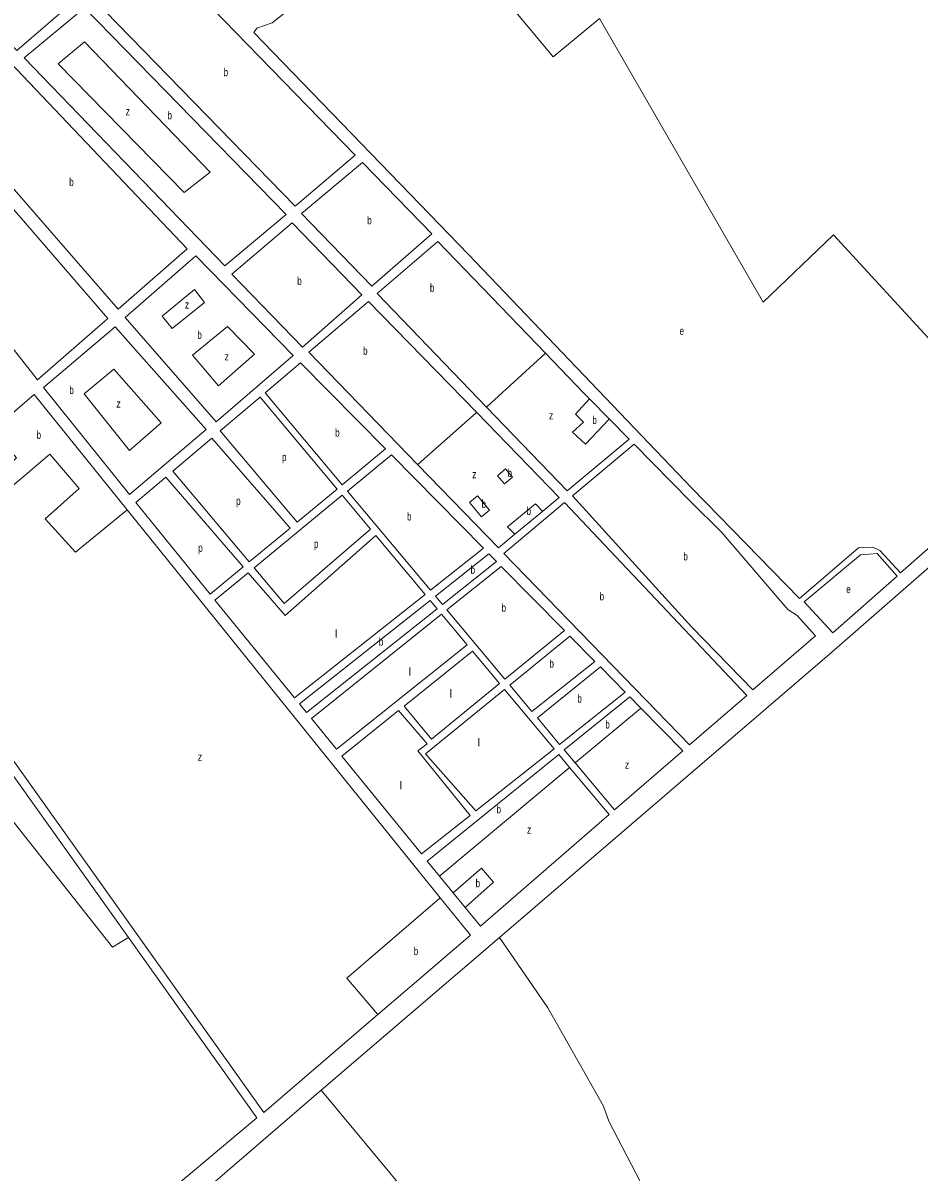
# Model space of a CAD drawing. Extents: x 639657 to 671642, y 222838 to 252123.
# Drawn here: x 656164 to 657284, y 229541 to 230977 of the extents above; entities that cross this region are included whole.
import ezdxf

# ---------------------------------------------------------------- set-up
doc = ezdxf.new("R2010")
doc.units = 0
doc.header["$LTSCALE"] = 4
doc.layers.add('1', color=7, linetype='Continuous', lineweight=13)
doc.layers.add('21', color=7, linetype='Continuous', lineweight=13)
doc.layers.add('7', color=7, linetype='Continuous')

msp = doc.modelspace()

# ---------------------------------------------------------------- linework, layer by layer
at = {"layer": '1'}
for p, q in [((656466.939, 230514.9), (656563.274, 230399.934)), ((656460.885, 230509.763), (656410.874, 230467.339)), ((656460.885, 230509.763), (656556.984, 230394.728)), ((656834.7, 230384.405), (656731.124, 230490.676)), ((656400.479, 230458.522), (656351.528, 230416.996)), ((656400.479, 230458.522), (656498.204, 230346.074)), ((656410.874, 230467.339), (656506.996, 230353.351)), ((656844.557, 230392.588), (656922.134, 230457)), ((656563.274, 230399.934), (656617.528, 230444.841)), ((656851.041, 230386.083), (656928.324, 230450.708)), ((656569.813, 230392.13), (656624.857, 230437.403)), ((656739.864, 230320.684), (656624.857, 230437.403)), ((656351.528, 230416.996), (656446.958, 230303.656)), ((656342.85, 230409.634), (656439.588, 230297.556)), ((656453.211, 230296.229), (656563.495, 230386.934)), ((656506.996, 230353.351), (656556.984, 230394.728)), ((656563.495, 230386.934), (656598.727, 230344.759)), ((656569.813, 230392.13), (656673.59, 230268.281)), ((656765.331, 230314.412), (656841.091, 230377.763)), ((657068.838, 230136.938), (656841.091, 230377.763)), ((656446.958, 230303.656), (656498.204, 230346.074)), ((656605.389, 230336.784), (656666.982, 230263.055)), ((656673.59, 230268.281), (656739.864, 230320.684)), ((656679.79, 230260.882), (656746.571, 230313.877)), ((656756.142, 230304.163), (656746.571, 230313.877)), ((656765.331, 230314.412), (656997.493, 230075.051)), ((656398.351, 230263.424), (656439.588, 230297.556)), ((656688.536, 230250.444), (656756.142, 230304.163)), ((656694.223, 230243.658), (656762.094, 230298.122)), ((656841.125, 230217.915), (656762.094, 230298.122)), ((656404.353, 230256.045), (656445.913, 230290.228)), ((656404.353, 230256.045), (656503.684, 230133.934)), ((656503.684, 230133.934), (656666.982, 230263.055)), ((656510.013, 230126.152), (656673.18, 230255.635)), ((656673.18, 230255.635), (656681.913, 230245.182)), ((656679.79, 230260.882), (656688.536, 230250.444)), ((656518.689, 230115.487), (656681.913, 230245.182)), ((656694.223, 230243.658), (656766.714, 230157.147)), ((656524.933, 230107.811), (656687.615, 230238.356)), ((656687.615, 230238.356), (656719.63, 230200.033)), ((656841.125, 230217.915), (656766.714, 230157.147)), ((656847.837, 230211.103), (656772.829, 230149.847)), ((656879.197, 230179.276), (656847.837, 230211.103)), ((656556.046, 230069.563), (656719.63, 230200.033)), ((656640.632, 230123.355), (656726.173, 230192.201)), ((656726.173, 230192.201), (656760.022, 230151.683)), ((656800.522, 230116.799), (656879.197, 230179.276)), ((656807.23, 230108.793), (656886.01, 230172.362)), ((656917.104, 230140.806), (656886.01, 230172.362)), ((656766.128, 230144.374), (656667.597, 230063.908)), ((656760.022, 230151.683), (656674.921, 230082.184)), ((656766.128, 230144.374), (656828.094, 230070.198)), ((656772.829, 230149.847), (656800.522, 230116.799)), ((656834.988, 230075.667), (656917.104, 230140.806)), ((656510.013, 230126.152), (656518.689, 230115.487)), ((656840.884, 230068.63), (656922.804, 230135.02)), ((656997.493, 230075.051), (657068.838, 230136.938)), ((656563.068, 230060.931), (656633.741, 230117.809)), ((656633.741, 230117.809), (656669.368, 230076.412)), ((656640.632, 230123.355), (656674.921, 230082.184)), ((656524.933, 230107.811), (656556.046, 230069.563)), ((656807.23, 230108.793), (656834.988, 230075.667)), ((656730.177, 229992.524), (656828.094, 230070.198)), ((656563.068, 230060.931), (656662.429, 229938.783)), ((656667.597, 230063.908), (656730.177, 229992.524)), ((656669.674, 229929.876), (656834.039, 230063.083)), ((656662.429, 229938.783), (656723.134, 229986.938)), ((656736.052, 229848.275), (656896.919, 229987.813)), ((656667.82, 229789.09), (656723.507, 229837.393))]:
    msp.add_line(p, q, dxfattribs=at)
for points in [[(656231.52, 231007.4), (656156.92, 230942.74), (656030.9, 231074.47), (656105.5, 231139.55)], [(656251.18, 231008.67), (656325.79, 231073.33), (656579.74, 230812.26), (656504.7, 230748.23)], [(656166.13, 230933.81), (656241.2, 230996.12), (656493.19, 230737.82), (656416.86, 230673.55)], [(655984, 230783.98), (656182.67, 230531.42), (656270.29, 230607.82), (656061.4, 230849.76)], [(656512.3, 230739.27), (656600.34, 230648.27), (656675.37, 230713.81), (656588.63, 230803.1)], [(656513.8, 230572.3), (656587.98, 230637.42), (656500.8, 230727.56), (656425.33, 230663.52)], [(656502.13, 230561.8), (656405.75, 230478.75), (656291.97, 230609.3), (656380.44, 230686.35)], [(656393.24, 230468.99), (656297.76, 230388.07), (656190.28, 230521.6), (656279.62, 230597.59)], [(657256.82, 230285.76), (657176.49, 230215.12), (657140.47, 230253.8), (657211, 230312.6), (657232.02, 230314.39)]]:
    msp.add_lwpolyline(points, close=True, dxfattribs=at)
for points in [[(656713.006, 231072.175), (656690.32, 231055.59), (656656.04, 231046.06), (656645.94, 231046.4), (656621.85, 231048.99), (656588.33, 231049.99), (656562.8, 231046.55), (656475.94, 230977.58), (656456.79, 230970.95), (656453.1, 230965.47), (656721.14, 230687.77), (657000.35, 230395.98), (657134.77, 230258.17), (657208.41, 230321.35), (657226.66, 230322.21), (657235.15, 230318.12), (657261.23, 230289.95), (657389.09, 230402.13), (657419.13, 230421.32), (657433.542, 230433.621)], [(656121.755, 230903.589), (656149, 230927.43), (656369.62, 230695.06), (656283.5, 230619.54), (656073.12, 230861.03)], [(656817.466, 230564.471), (656682.97, 230704.21), (656606.87, 230639.08), (656743.663, 230497.22), (656844.557, 230392.588)], [(656731.124, 230490.676), (656596.21, 230629.1), (656521.59, 230565.71), (656657.856, 230425.219), (656758.67, 230321.279)], [(656872.378, 230507.581), (656865.11, 230514.97), (656817.466, 230564.471)], [(656617.528, 230444.841), (656511.364, 230552.586), (656466.939, 230514.9)], [(656294.805, 230368.746), (656178.33, 230513.11), (656126.46, 230468.312)], [(656922.134, 230457), (656897.171, 230482.377), (656872.378, 230507.581)], [(657076.684, 230143.743), (657154.66, 230211.38), (657132.09, 230236.84), (657120.29, 230244.08), (657037.66, 230340.52), (656998.33, 230379.54), (656928.324, 230450.708)], [(656342.85, 230409.634), (656305.317, 230377.794), (656398.351, 230263.424)], [(656758.67, 230321.279), (656779.18, 230338.308), (656813.934, 230367.163), (656834.7, 230384.405)], [(656759.781, 229834.397), (657175.31, 230190.97), (657402.74, 230389.56)], [(656851.041, 230386.083), (657000.44, 230222.18), (657076.684, 230143.743)], [(656723.507, 229837.393), (656685.987, 229883.897), (656294.805, 230368.746)], [(656453.211, 230296.229), (656490.819, 230251.562), (656598.727, 230344.759)], [(656445.913, 230290.228), (656491.946, 230236.895), (656605.389, 230336.784)], [(656036.359, 230217.808), (656047.48, 230202.27), (656465.47, 229615.693)], [(656456.848, 229608.823), (656296.108, 229834.173), (656058.678, 230167.038)], [(655731.897, 230145.996), (655783.11, 230068.23), (655825.65, 229999.78), (656081.6, 229620.02), (656101.05, 229582.51), (656215.39, 229416.21), (656215.1, 229406.11), (656456.848, 229608.823)], [(656903.686, 229993.682), (656989.082, 230067.756), (656936.676, 230120.941), (656922.804, 230135.02)], [(656669.368, 230076.412), (656657.702, 230067.658), (656723.134, 229986.938)], [(656840.884, 230068.63), (656854.376, 230052.529), (656903.686, 229993.682)], [(656834.039, 230063.083), (656847.584, 230046.869), (656896.919, 229987.813)], [(656669.674, 229929.876), (656684.974, 229911.068), (656701.912, 229890.244), (656716.972, 229871.731), (656736.052, 229848.275)], [(656268.075, 229417.933), (656389.44, 229516.6), (656537.178, 229643.377), (656759.781, 229834.397)], [(656465.47, 229615.693), (656608.013, 229737.84), (656667.82, 229789.09)]]:
    msp.add_lwpolyline(points, dxfattribs=at)
at = {"layer": '21'}
for points in [[(656885.059, 230982.984), (656884.559, 230982.57), (656826.983, 230934.888), (656713.421, 231071.675), (656713.006, 231072.175)], [(656885.059, 230982.984), (657089.328, 230628.277), (657177.444, 230712.445), (657433.083, 230434.121), (657433.542, 230433.621)], [(656743.663, 230497.22), (656744.163, 230497.676), (656816.966, 230564.015), (656817.466, 230564.471)], [(656872.378, 230507.581), (656871.841, 230506.998), (656854.771, 230488.496), (656864.746, 230478.514), (656851.03, 230466.038), (656867.24, 230451.066), (656896.693, 230481.877), (656897.171, 230482.377)], [(656657.856, 230425.219), (656658.356, 230425.666), (656730.624, 230490.229), (656731.124, 230490.676)], [(656126.46, 230468.312), (656126.891, 230467.812), (656156.253, 230433.731), (656136.617, 230415.238), (656150.478, 230397.902), (656197.836, 230438.354), (656234.799, 230395.59), (656192.061, 230357.45), (656230.179, 230315.842), (656294.305, 230368.337), (656294.805, 230368.746)], [(656779.18, 230338.308), (656778.68, 230338.808), (656769.981, 230347.512), (656804.895, 230376.208), (656813.434, 230367.663), (656813.934, 230367.163)], [(656058.678, 230167.038), (656058.178, 230166.653), (656022.263, 230139.01), (656063.846, 230090.468), (656276.382, 229822.33), (656295.608, 229833.873), (656296.108, 229834.173)], [(656854.376, 230052.529), (656854.876, 230052.945), (656936.176, 230120.525), (656936.676, 230120.941)], [(656684.974, 229911.068), (656685.474, 229911.486), (656847.084, 230046.451), (656847.584, 230046.869)], [(656701.912, 229890.244), (656702.412, 229890.673), (656737.561, 229920.818), (656752.524, 229903.351), (656717.472, 229872.176), (656716.972, 229871.731)], [(656685.987, 229883.897), (656685.487, 229883.467), (656569.228, 229783.577), (656607.589, 229738.34), (656608.013, 229737.84)], [(656759.781, 229834.397), (656820.267, 229746.459), (656889.818, 229623.28), (656896.576, 229604.797), (656974.841, 229454.039), (657057.261, 229275.713), (657056.349, 229262.078), (657129.811, 229104.099)], [(656587.752, 229331.936), (656703.258, 229425.966), (656688.31, 229461.23), (656537.178, 229643.377)]]:
    msp.add_lwpolyline(points, dxfattribs=at)
for points in [[(656208.595, 230926.259), (656365.904, 230765.436), (656398.246, 230790.863), (656241.154, 230953.826)], [(656338.228, 230611.021), (656350.888, 230595.539), (656391.316, 230627.9), (656378.61, 230644.081)], [(656376.352, 230561.959), (656408.643, 230523.881), (656453.691, 230563.177), (656420.193, 230597.85)], [(656240.877, 230513.847), (656297.754, 230442.977), (656337.027, 230477.65), (656278.118, 230544.685)], [(656767.487, 230419.875), (656776.205, 230409.699), (656766.24, 230401.161), (656757.522, 230411.337)], [(656732.574, 230386.189), (656747.501, 230368.266), (656737.561, 230359.988), (656722.634, 230377.911)]]:
    msp.add_lwpolyline(points, close=True, dxfattribs=at)

# ---------------------------------------------------------------- texts
at = {"layer": '7'}
for s, width, p in [('b', 0.75, (656415.188, 230910.78)), ('z', 0.8, (656292.8, 230861.886)), ('b', 0.75, (656345.029, 230856.794)), ('b', 0.75, (656222.274, 230773.485)), ('b', 0.75, (656594.639, 230725.685)), ('b', 0.75, (656507.196, 230649.93)), ('b', 0.75, (656673.035, 230641.197)), ('z', 0.8, (656366.725, 230620.33)), ('b', 0.75, (656382.399, 230582.55)), ('e', 0.75, (656984.998, 230587.398)), ('b', 0.75, (656589.492, 230562.595)), ('z', 0.8, (656416.394, 230555.607)), ('b', 0.75, (656222.347, 230513.634)), ('z', 0.8, (656281.249, 230496.663)), ('z', 0.8, (656821.808, 230481.854)), ('b', 0.75, (656875.968, 230476.019)), ('b', 0.75, (656554.579, 230460.288)), ('b', 0.75, (656181.374, 230457.539)), ('p', 0.75, (656488.18, 230429.855)), ('z', 0.8, (656725.796, 230408.243)), ('b', 0.75, (656769.981, 230409.894)), ('p', 0.75, (656430.822, 230374.959)), ('b', 0.75, (656737.561, 230371.217)), ('b', 0.75, (656793.672, 230362.484)), ('b', 0.75, (656644.356, 230355.486)), ('p', 0.75, (656528.081, 230321.31)), ('p', 0.75, (656383.44, 230316.32)), ('b', 0.75, (656989.75, 230305.581)), ('b', 0.75, (656723.845, 230288.873)), ('e', 0.75, (657193.272, 230264.755)), ('b', 0.75, (656885.009, 230255.675)), ('b', 0.75, (656762.5, 230241.462)), ('b', 0.75, (656609.13, 230199.042)), ('b', 0.75, (656822.351, 230171.594)), ('b', 0.75, (656857.265, 230127.927)), ('b', 0.75, (656892.178, 230095.488)), ('z', 0.8, (656382.897, 230055.16)), ('z', 0.8, (656916.573, 230045.179)), ('b', 0.75, (656756.265, 229989.438)), ('z', 0.8, (656794.376, 229964.082)), ('b', 0.75, (656730.08, 229897.113)), ('b', 0.75, (656652.772, 229812.273))]:
    msp.add_text(s, height=10, dxfattribs=dict(at, width=width)).set_placement(p)
for p in [(656554.266, 230209.023), (656646.537, 230161.613), (656697.66, 230134.164), (656732.574, 230073.03), (656635.315, 230019.381)]:
    msp.add_text('l', height=10, dxfattribs=at).set_placement(p)

doc.saveas('drawing.dxf')
